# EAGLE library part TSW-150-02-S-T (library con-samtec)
THROUGH-HOLE .025" SQ POST HEADER Source: Samtec TSW.pdf
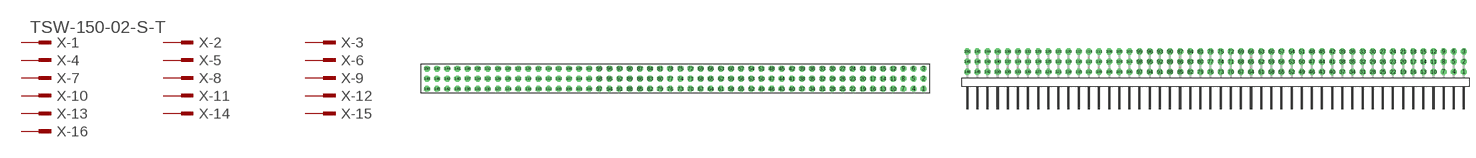
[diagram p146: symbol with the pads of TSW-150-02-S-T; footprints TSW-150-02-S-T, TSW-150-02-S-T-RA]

Designator prefix X; gates -1=MPINV -2=MPIN -3=MPIN -4=MPIN -5=MPIN -6=MPIN -7=MPIN -8=MPIN -9=MPIN -10=MPIN -11=MPIN -12=MPIN -13=MPIN -14=MPIN -15=MPIN -16=MPIN -17=MPIN -18=MPIN -19=MPIN -20=MPIN -21=MPIN -22=MPIN -23=MPIN -24=MPIN -25=MPIN -26=MPIN -27=MPIN -28=MPIN -29=MPIN -30=MPIN -31=MPIN -32=MPIN -33=MPIN -34=MPIN -35=MPIN -36=MPIN -37=MPIN -38=MPIN -39=MPIN -40=MPIN -41=MPIN -42=MPIN -43=MPIN -44=MPIN -45=MPIN -46=MPIN -47=MPIN -48=MPIN -49=MPIN -50=MPIN -51=MPIN -52=MPIN -53=MPIN -54=MPIN -55=MPIN -56=MPIN -57=MPIN -58=MPIN -59=MPIN -60=MPIN -61=MPIN -62=MPIN -63=MPIN -64=MPIN -65=MPIN -66=MPIN -67=MPIN -68=MPIN -69=MPIN -70=MPIN -71=MPIN -72=MPIN -73=MPIN -74=MPIN -75=MPIN -76=MPIN -77=MPIN -78=MPIN -79=MPIN -80=MPIN -81=MPIN -82=MPIN -83=MPIN -84=MPIN -85=MPIN -86=MPIN -87=MPIN -88=MPIN -89=MPIN -90=MPIN -91=MPIN -92=MPIN -93=MPIN -94=MPIN -95=MPIN -96=MPIN -97=MPIN -98=MPIN -99=MPIN -100=MPIN -101=MPIN -102=MPIN -103=MPIN -104=MPIN -105=MPIN -106=MPIN -107=MPIN -108=MPIN -109=MPIN -110=MPIN -111=MPIN -112=MPIN -113=MPIN -114=MPIN -115=MPIN -116=MPIN -117=MPIN -118=MPIN -119=MPIN -120=MPIN -121=MPIN -122=MPIN -123=MPIN -124=MPIN -125=MPIN -126=MPIN -127=MPIN -128=MPIN -129=MPIN -130=MPIN -131=MPIN -132=MPIN -133=MPIN -134=MPIN -135=MPIN -136=MPIN -137=MPIN -138=MPIN -139=MPIN -140=MPIN -141=MPIN -142=MPIN -143=MPIN -144=MPIN -145=MPIN -146=MPIN -147=MPIN -148=MPIN -149=MPIN -150=MPIN

## TSW-150-02-S-T (OC_FARNELL: unknown; OC_NEWARK: unknown)  [TSW-150-02-S-T]
1  -1:1  pas
2  -2:1  pas
3  -3:1  pas
4  -4:1  pas
5  -5:1  pas
6  -6:1  pas
7  -7:1  pas
8  -8:1  pas
9  -9:1  pas
10  -10:1  pas
11  -11:1  pas
12  -12:1  pas
13  -13:1  pas
14  -14:1  pas
15  -15:1  pas
16  -16:1  pas
17  -17:1  pas
18  -18:1  pas
19  -19:1  pas
20  -20:1  pas
21  -21:1  pas
22  -22:1  pas
23  -23:1  pas
24  -24:1  pas
25  -25:1  pas
26  -26:1  pas
27  -27:1  pas
28  -28:1  pas
29  -29:1  pas
30  -30:1  pas
31  -31:1  pas
32  -32:1  pas
33  -33:1  pas
34  -34:1  pas
35  -35:1  pas
36  -36:1  pas
37  -37:1  pas
38  -38:1  pas
39  -39:1  pas
40  -40:1  pas
41  -41:1  pas
42  -42:1  pas
43  -43:1  pas
44  -44:1  pas
45  -45:1  pas
46  -46:1  pas
47  -47:1  pas
48  -48:1  pas
49  -49:1  pas
50  -50:1  pas
51  -51:1  pas
52  -52:1  pas
53  -53:1  pas
54  -54:1  pas
55  -55:1  pas
56  -56:1  pas
57  -57:1  pas
58  -58:1  pas
59  -59:1  pas
60  -60:1  pas
61  -61:1  pas
62  -62:1  pas
63  -63:1  pas
64  -64:1  pas
65  -65:1  pas
66  -66:1  pas
67  -67:1  pas
68  -68:1  pas
69  -69:1  pas
70  -70:1  pas
71  -71:1  pas
72  -72:1  pas
73  -73:1  pas
74  -74:1  pas
75  -75:1  pas
76  -76:1  pas
77  -77:1  pas
78  -78:1  pas
79  -79:1  pas
80  -80:1  pas
81  -81:1  pas
82  -82:1  pas
83  -83:1  pas
84  -84:1  pas
85  -85:1  pas
86  -86:1  pas
87  -87:1  pas
88  -88:1  pas
89  -89:1  pas
90  -90:1  pas
91  -91:1  pas
92  -92:1  pas
93  -93:1  pas
94  -94:1  pas
95  -95:1  pas
96  -96:1  pas
97  -97:1  pas
98  -98:1  pas
99  -99:1  pas
100  -100:1  pas
101  -101:1  pas
102  -102:1  pas
103  -103:1  pas
104  -104:1  pas
105  -105:1  pas
106  -106:1  pas
107  -107:1  pas
108  -108:1  pas
109  -109:1  pas
110  -110:1  pas
111  -111:1  pas
112  -112:1  pas
113  -113:1  pas
114  -114:1  pas
115  -115:1  pas
116  -116:1  pas
117  -117:1  pas
118  -118:1  pas
119  -119:1  pas
120  -120:1  pas
121  -121:1  pas
122  -122:1  pas
123  -123:1  pas
124  -124:1  pas
125  -125:1  pas
126  -126:1  pas
127  -127:1  pas
128  -128:1  pas
129  -129:1  pas
130  -130:1  pas
131  -131:1  pas
132  -132:1  pas
133  -133:1  pas
134  -134:1  pas
135  -135:1  pas
136  -136:1  pas
137  -137:1  pas
138  -138:1  pas
139  -139:1  pas
140  -140:1  pas
141  -141:1  pas
142  -142:1  pas
143  -143:1  pas
144  -144:1  pas
145  -145:1  pas
146  -146:1  pas
147  -147:1  pas
148  -148:1  pas
149  -149:1  pas
150  -150:1  pas

## TSW-150-02-S-T-RA (OC_FARNELL: unknown; OC_NEWARK: unknown)  [TSW-150-02-S-T-RA]
Pads as for TSW-150-02-S-T

## Footprint TSW-150-02-S-T (pad centres in mm)
THROUGH-HOLE .025" SQ POST HEADER Source: Samtec TSW.pdf
drill 1 pad 1.5 octagon: 1 62.23,-2.54; 2 62.23,0; 3 62.23,2.54; 4 59.69,-2.54; 5 59.69,0; 6 59.69,2.54; 7 57.15,-2.54; 8 57.15,0; 9 57.15,2.54; 10 54.61,-2.54; 11 54.61,0; 12 54.61,2.54; 13 52.07,-2.54; 14 52.07,0; 15 52.07,2.54; 16 49.53,-2.54; 17 49.53,0; 18 49.53,2.54; 19 46.99,-2.54; 20 46.99,0; 21 46.99,2.54; 22 44.45,-2.54; 23 44.45,0; 24 44.45,2.54; 25 41.91,-2.54; 26 41.91,0; 27 41.91,2.54; 28 39.37,-2.54; 29 39.37,0; 30 39.37,2.54; 31 36.83,-2.54; 32 36.83,0; 33 36.83,2.54; 34 34.29,-2.54; 35 34.29,0; 36 34.29,2.54; 37 31.75,-2.54; 38 31.75,0; 39 31.75,2.54; 40 29.21,-2.54; 41 29.21,0; 42 29.21,2.54; 43 26.67,-2.54; 44 26.67,0; 45 26.67,2.54; 46 24.13,-2.54; 47 24.13,0; 48 24.13,2.54; 49 21.59,-2.54; 50 21.59,0; 51 21.59,2.54; 52 19.05,-2.54; 53 19.05,0; 54 19.05,2.54; 55 16.51,-2.54; 56 16.51,0; 57 16.51,2.54; 58 13.97,-2.54; 59 13.97,0; 60 13.97,2.54; 61 11.43,-2.54; 62 11.43,0; 63 11.43,2.54; 64 8.89,-2.54; 65 8.89,0; 66 8.89,2.54; 67 6.35,-2.54; 68 6.35,0; 69 6.35,2.54; 70 3.81,-2.54; 71 3.81,0; 72 3.81,2.54; 73 1.27,-2.54; 74 1.27,0; 75 1.27,2.54; 76 -1.27,-2.54; 77 -1.27,0; 78 -1.27,2.54; 79 -3.81,-2.54; 80 -3.81,0; 81 -3.81,2.54; 82 -6.35,-2.54; 83 -6.35,0; 84 -6.35,2.54; 85 -8.89,-2.54; 86 -8.89,0; 87 -8.89,2.54; 88 -11.43,-2.54; 89 -11.43,0; 90 -11.43,2.54; 91 -13.97,-2.54; 92 -13.97,0; 93 -13.97,2.54; 94 -16.51,-2.54; 95 -16.51,0; 96 -16.51,2.54; 97 -19.05,-2.54; 98 -19.05,0; 99 -19.05,2.54; 100 -21.59,-2.54; 101 -21.59,0; 102 -21.59,2.54; 103 -24.13,-2.54; 104 -24.13,0; 105 -24.13,2.54; 106 -26.67,-2.54; 107 -26.67,0; 108 -26.67,2.54; 109 -29.21,-2.54; 110 -29.21,0; 111 -29.21,2.54; 112 -31.75,-2.54; 113 -31.75,0; 114 -31.75,2.54; 115 -34.29,-2.54; 116 -34.29,0; 117 -34.29,2.54; 118 -36.83,-2.54; 119 -36.83,0; 120 -36.83,2.54; 121 -39.37,-2.54; 122 -39.37,0; 123 -39.37,2.54; 124 -41.91,-2.54; 125 -41.91,0; 126 -41.91,2.54; 127 -44.45,-2.54; 128 -44.45,0; 129 -44.45,2.54; 130 -46.99,-2.54; 131 -46.99,0; 132 -46.99,2.54; 133 -49.53,-2.54; 134 -49.53,0; 135 -49.53,2.54; 136 -52.07,-2.54; 137 -52.07,0; 138 -52.07,2.54; 139 -54.61,-2.54; 140 -54.61,0; 141 -54.61,2.54; 142 -57.15,-2.54; 143 -57.15,0; 144 -57.15,2.54; 145 -59.69,-2.54; 146 -59.69,0; 147 -59.69,2.54; 148 -62.23,-2.54; 149 -62.23,0; 150 -62.23,2.54

## Footprint TSW-150-02-S-T-RA (pad centres in mm)
THROUGH-HOLE .025" SQ POST HEADER Source: SamtechTSW.pdf
drill 1 pad 1.5 octagon: 1 62.23,1.524; 2 62.23,4.064; 3 62.23,6.604; 4 59.69,1.524; 5 59.69,4.064; 6 59.69,6.604; 7 57.15,1.524; 8 57.15,4.064; 9 57.15,6.604; 10 54.61,1.524; 11 54.61,4.064; 12 54.61,6.604; 13 52.07,1.524; 14 52.07,4.064; 15 52.07,6.604; 16 49.53,1.524; 17 49.53,4.064; 18 49.53,6.604; 19 46.99,1.524; 20 46.99,4.064; 21 46.99,6.604; 22 44.45,1.524; 23 44.45,4.064; 24 44.45,6.604; 25 41.91,1.524; 26 41.91,4.064; 27 41.91,6.604; 28 39.37,1.524; 29 39.37,4.064; 30 39.37,6.604; 31 36.83,1.524; 32 36.83,4.064; 33 36.83,6.604; 34 34.29,1.524; 35 34.29,4.064; 36 34.29,6.604; 37 31.75,1.524; 38 31.75,4.064; 39 31.75,6.604; 40 29.21,1.524; 41 29.21,4.064; 42 29.21,6.604; 43 26.67,1.524; 44 26.67,4.064; 45 26.67,6.604; 46 24.13,1.524; 47 24.13,4.064; 48 24.13,6.604; 49 21.59,1.524; 50 21.59,4.064; 51 21.59,6.604; 52 19.05,1.524; 53 19.05,4.064; 54 19.05,6.604; 55 16.51,1.524; 56 16.51,4.064; 57 16.51,6.604; 58 13.97,1.524; 59 13.97,4.064; 60 13.97,6.604; 61 11.43,1.524; 62 11.43,4.064; 63 11.43,6.604; 64 8.89,1.524; 65 8.89,4.064; 66 8.89,6.604; 67 6.35,1.524; 68 6.35,4.064; 69 6.35,6.604; 70 3.81,1.524; 71 3.81,4.064; 72 3.81,6.604; 73 1.27,1.524; 74 1.27,4.064; 75 1.27,6.604; 76 -1.27,1.524; 77 -1.27,4.064; 78 -1.27,6.604; 79 -3.81,1.524; 80 -3.81,4.064; 81 -3.81,6.604; 82 -6.35,1.524; 83 -6.35,4.064; 84 -6.35,6.604; 85 -8.89,1.524; 86 -8.89,4.064; 87 -8.89,6.604; 88 -11.43,1.524; 89 -11.43,4.064; 90 -11.43,6.604; 91 -13.97,1.524; 92 -13.97,4.064; 93 -13.97,6.604; 94 -16.51,1.524; 95 -16.51,4.064; 96 -16.51,6.604; 97 -19.05,1.524; 98 -19.05,4.064; 99 -19.05,6.604; 100 -21.59,1.524; 101 -21.59,4.064; 102 -21.59,6.604; 103 -24.13,1.524; 104 -24.13,4.064; 105 -24.13,6.604; 106 -26.67,1.524; 107 -26.67,4.064; 108 -26.67,6.604; 109 -29.21,1.524; 110 -29.21,4.064; 111 -29.21,6.604; 112 -31.75,1.524; 113 -31.75,4.064; 114 -31.75,6.604; 115 -34.29,1.524; 116 -34.29,4.064; 117 -34.29,6.604; 118 -36.83,1.524; 119 -36.83,4.064; 120 -36.83,6.604; 121 -39.37,1.524; 122 -39.37,4.064; 123 -39.37,6.604; 124 -41.91,1.524; 125 -41.91,4.064; 126 -41.91,6.604; 127 -44.45,1.524; 128 -44.45,4.064; 129 -44.45,6.604; 130 -46.99,1.524; 131 -46.99,4.064; 132 -46.99,6.604; 133 -49.53,1.524; 134 -49.53,4.064; 135 -49.53,6.604; 136 -52.07,1.524; 137 -52.07,4.064; 138 -52.07,6.604; 139 -54.61,1.524; 140 -54.61,4.064; 141 -54.61,6.604; 142 -57.15,1.524; 143 -57.15,4.064; 144 -57.15,6.604; 145 -59.69,1.524; 146 -59.69,4.064; 147 -59.69,6.604; 148 -62.23,1.524; 149 -62.23,4.064; 150 -62.23,6.604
